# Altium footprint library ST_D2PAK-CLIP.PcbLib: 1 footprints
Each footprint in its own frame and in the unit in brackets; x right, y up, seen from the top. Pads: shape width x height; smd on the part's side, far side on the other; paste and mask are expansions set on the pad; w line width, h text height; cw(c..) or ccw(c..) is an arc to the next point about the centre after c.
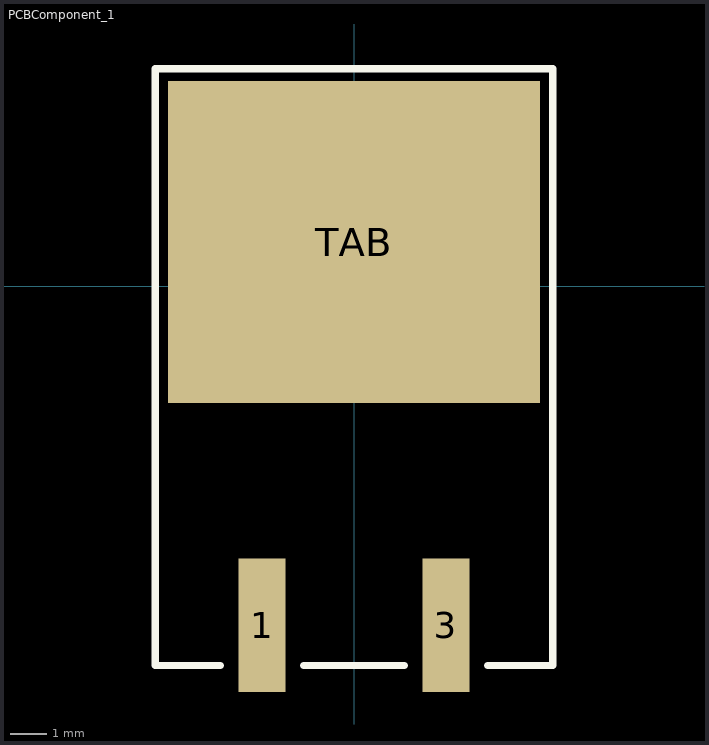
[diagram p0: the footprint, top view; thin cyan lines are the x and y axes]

## PCBComponent_1 [mm]
pads (3):
  rect 1.3x3.7 smd: 1(-2.54,-9.38) 3(2.54,-9.38)
  rect 10.3x8.9 smd: TAB(0,1.22)
Top Overlay:
  lines w0.2: -3.7,-10.49 -5.5,-10.49 -5.5,6.01 5.5,6.01 5.5,-10.49 3.7,-10.49 ; -1.4,-10.49 1.4,-10.49
3D body "ST_D2PAK-CLIP.step": height 4.5, standoff 0, extent -5.14,-10.16 5.14,5.21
